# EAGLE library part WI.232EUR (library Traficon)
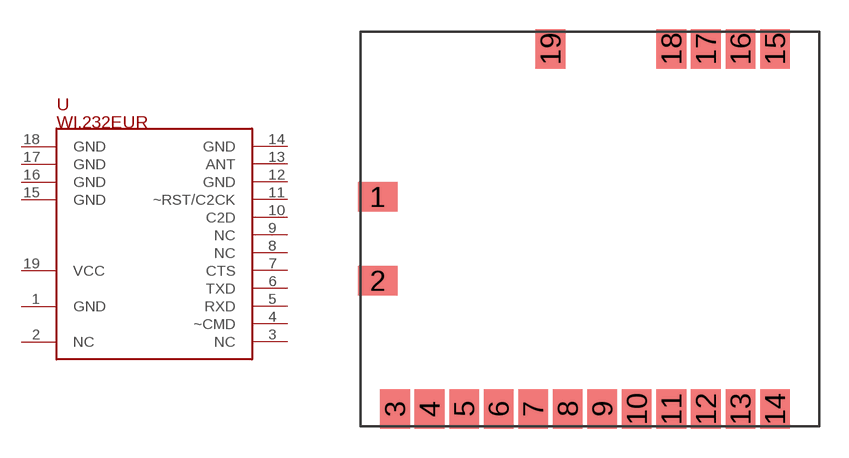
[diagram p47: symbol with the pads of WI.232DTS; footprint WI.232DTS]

Designator prefix U

## WI.232EUR  [WI.232DTS]
1  GND
2  NC
3  NC
4  ~CMD
5  RXD
6  TXD
7  CTS
8  NC
9  NC
10  C2D
11  ~RST/C2CK
12  GND
13  ANT
14  GND
15  GND
16  GND
17  GND
18  GND
19  VCC

## Footprint WI.232DTS (pad centres in mm)
smd 2.032 x 1.524: 1 0.889,11.811; 2 0.889,7.493
smd 1.524 x 2.032: 3 1.778,0.889; 4 3.556,0.889; 5 5.334,0.889; 6 7.112,0.889; 7 8.89,0.889; 8 10.668,0.889; 9 12.446,0.889; 10 14.224,0.889; 11 16.002,0.889; 12 17.78,0.889; 13 19.558,0.889; 14 21.336,0.889; 15 21.336,19.431; 16 19.558,19.431; 17 17.78,19.431; 18 16.002,19.431; 19 9.779,19.431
